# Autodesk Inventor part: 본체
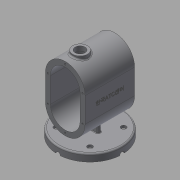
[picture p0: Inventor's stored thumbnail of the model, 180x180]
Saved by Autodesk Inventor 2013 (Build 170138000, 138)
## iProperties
Created: 2016-12
Part Number: 본체
Material: 일반
Document SubType Name: Modeling
Designer: mduedu
Density: 1 g/cm^3
Author: mduedu
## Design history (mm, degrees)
sketch "스케치1"
  geometry: L1 (40, -25)-(40, 25); L2 (-40, 25)-(-40, -25); L3 (-40, -25)-(40, 25); L4 (40, -25)-(-40, 25); L5 (0, 25)-(0, -25); A1 r 40 centre (0, 25) between (40, 25) and (-40, 25); A2 r 40 centre (0, -25) between (-40, -25) and (40, -25); 1 further point
  constraints: 10 end point, 4 point on circle, 3 tangent, 2 centre point, 2 midpoint, 2 parallel, 1 vertical
  dimensions: "d0" = 130 dimension on A2 A1; "d2" = 80 distance between parallel lines of L1 L2
extrude "돌출1" new body sketch "스케치1" stored distance "d3" = 100; taper "d4" = 0 deg
feature "쉘1" dims "d5" = 10
sketch "스케치2"
  geometry: L1 (-75, 65)-(-90, 65); L2 (-90, 65)-(-90, 0); L3 (-75, 0)-(-75, 65); L4 (-75, 0)-(-90, 0); 1 further point
  constraints: 8 end point, 1 horizontal, 1 horizontal alignment, 1 parallel, 1 perpendicular
  dimensions: "d6" = 90 distance from line of L2 point (0, 0); "d83" = 15 distance of L1.start L1.end; "d84" = 130 diameter of L1 L4
revolve "회전1" sketch "스케치2" stored, may be unused: angle "d85" = 90 deg
fillet "모깎기5" dims "d86" = 3
hole "구멍6" diameter "d89" = 120; stored, may be unused: countersink angle "d93" = 90 deg, drill point angle "d95" = 0 deg; dims "d87" = 10, "d88" = 10, "d90" = 6, "d91" = 4, "d92" = 2, "d94" = 10
sketch "스케치15"
  geometry: L1 (-90, -60)-(-90, 60) reference; C1 r 5 at (-90, 0); 1 further point
  constraints: 1 centre point, 1 horizontal alignment, 1 midpoint
  dimensions: "d96" = 10 diameter of C1
extrude "돌출6" cut sketch "스케치15" stored distance "d97" = 10; taper "d98" = 0 deg
sketch "스케치5"
  geometry: L1 (4, -30)-(-4, -30); L2 (-4, -30)-(-4, 30); L3 (-4, 30)-(4, 30); L4 (4, 30)-(4, -30); L5 (4, -30)-(-4, 30); L6 (-4, -30)-(4, 30); 3 further points
  constraints: 12 end point, 3 midpoint, 2 parallel, 1 coincident, 1 horizontal, 1 perpendicular
  dimensions: "d22" = 8 distance of L2.end L3.end; "d24" = 60 distance of L1.end L2.end
extrude "돌출3" join sketch "스케치5" stored distance "d25" = 80; taper "d26" = 0 deg
feature "면 기울기1" dims angle "d27" = 5 deg
sketch "스케치6"
  geometry: L1 (-18.718, -60.35)-(-20, -75); L2 (-62, -75)-(62, -75) reference; A1 r 40 centre (0, -25) between (-40, -25) and (40, -25) reference; 1 further point
  constraints: 2 end point, 1 point on circle, 1 point on line
  dimensions: "d28" = 20 horizontal distance of A1.centre L1.end; "d102" = 85 deg angle of L2 L1
feature "리브1" sketch "스케치6" dims "d30" = 1, "d31" = 8, "d32" = 0, "d33" = 0, "d34" = 1, "d35" = 1
fillet "모깎기2" dims "d36" = 3
fillet "모깎기3" dims "d37" = 1, "d38" = 1
node "작업 평면1"
sketch "스케치9"
  geometry: 1 further point
sketch "스케치7"
  geometry: L1 (40, 50)-(-40, 50) reference; C1 r 15 at (0, 20); 1 further point
  constraints: 1 centre point, 1 vertical alignment
  dimensions: "d40" = 30 diameter of C1; "d41" = 30 distance from line of C1.centre L1
extrude "돌출4" join sketch "스케치7" stored distance "d42" = 80; taper "d43" = 0 deg
hole "구멍2" diameter "d46" = 20; stored, may be unused: countersink angle "d50" = 90 deg, drill point angle "d52" = 118 deg; dims "d44" = 10, "d45" = 10, "d47" = 6, "d48" = 4, "d49" = 2, "d51" = 8
fillet "모깎기4" dims "d53" = 3
node "작업 평면2"
sketch "스케치8"
  geometry: C1 r 15 at (0, 0) reference; C2 r 15 at (0, 0); 1 further point
  constraints: 1 centre point, 1 coincident
  dimensions: "d55" = 30 diameter of C2
extrude "돌출5" cut sketch "스케치8" stored distance "d56" = 80; taper "d57" = 0 deg
chamfer "모따기1" distance "d58" = 1; stored, may be unused: second distance "d59" = 2, angle "d60" = 45 deg
sketch "스케치10"
  geometry: 2 further points
  constraints: 1 coincident, 1 other
feature "엠보싱1" sketch "스케치10" dims "d0" = 130, "d2" = 80, "d61" = 0.5, "d62" = 0
sketch "스케치11"
  geometry: 1 further point
hole "구멍3" sketch "스케치11" at (0, 60) diameter "d63" = 3.242; stored, may be unused: countersink angle "d67" = 90 deg, drill point angle "d69" = 120 deg; dims "d64" = 8.6, "d65" = 4, "d66" = 2, "d68" = 10.6
sketch "스케치12"
  geometry: 1 further point
hole "구멍5" sketch "스케치12" at (0, 60) diameter "d70" = 3.242; stored, may be unused: countersink angle "d74" = 90 deg, drill point angle "d76" = 120 deg; dims "d71" = 8.6, "d72" = 4, "d73" = 2, "d75" = 10.6
sketch "스케치16"
  geometry: L1 (0, 0)-(0, 48); L2 (0, 0)-(-33.941, 33.941); A1 r 48 centre (0, 0) between (0, 48) and (-33.941, 33.941); 2 further points
  constraints: 4 end point, 2 coincident, 2 point on circle, 1 centre point, 1 vertical
  dimensions: "d103" = 96 diameter of A1; "d104" = 45 deg angle of L1 L2
hole "구멍7" sketch "스케치16" at (-33.941, 33.941) diameter "d108" = 10; stored, may be unused: countersink angle "d112" = 90 deg, drill point angle "d114" = 118 deg; dims "d109" = 6, "d110" = 4, "d111" = 2, "d113" = 10
node "솔리드1"
pattern_circular "원형 패턴1" dims angle "d100" = 90 deg
mirror "대칭1"
pattern_linear "직사각형 패턴1"
pattern_linear "직사각형 패턴2"
pattern_circular "원형 패턴2" dims "d35" = 1, angle "d116" = 360 deg
sketch "스케치13"
  geometry: L1 (-40, 25)-(-40, -25) reference; L2 (40, -25)-(40, 25) reference; L3 (35, 25)-(35, -25); L4 (-35, -25)-(-35, 25); A1 r 40 centre (0, 25) between (40, 25) and (-40, 25) reference; A2 r 40 centre (0, -25) between (-40, -25) and (40, -25) reference; A3 r 35 centre (0, 25) between (35, 25) and (-35, 25); A4 r 35 centre (0, -25) between (-35, -25) and (35, -25); 2 further points
  constraints: 5 point on circle, 4 end point, 2 centre point, 3 other
  dimensions: "d77" = 5 distance between parallel lines of L3 L2
sketch "스케치14"
  geometry: L1 (-40, 25)-(-40, -25) reference; L2 (40, -25)-(40, 25) reference; L3 (35, 25)-(35, -25); L4 (-35, -25)-(-35, 25); A1 r 40 centre (0, 25) between (40, 25) and (-40, 25) reference; A2 r 40 centre (0, -25) between (-40, -25) and (40, -25) reference; A3 r 35 centre (0, 25) between (35, 25) and (-35, 25); A4 r 35 centre (0, -25) between (-35, -25) and (35, -25); 2 further points
  constraints: 5 point on circle, 4 end point, 2 centre point, 3 other
  dimensions: "d80" = 5 distance between parallel lines of L2 L3
